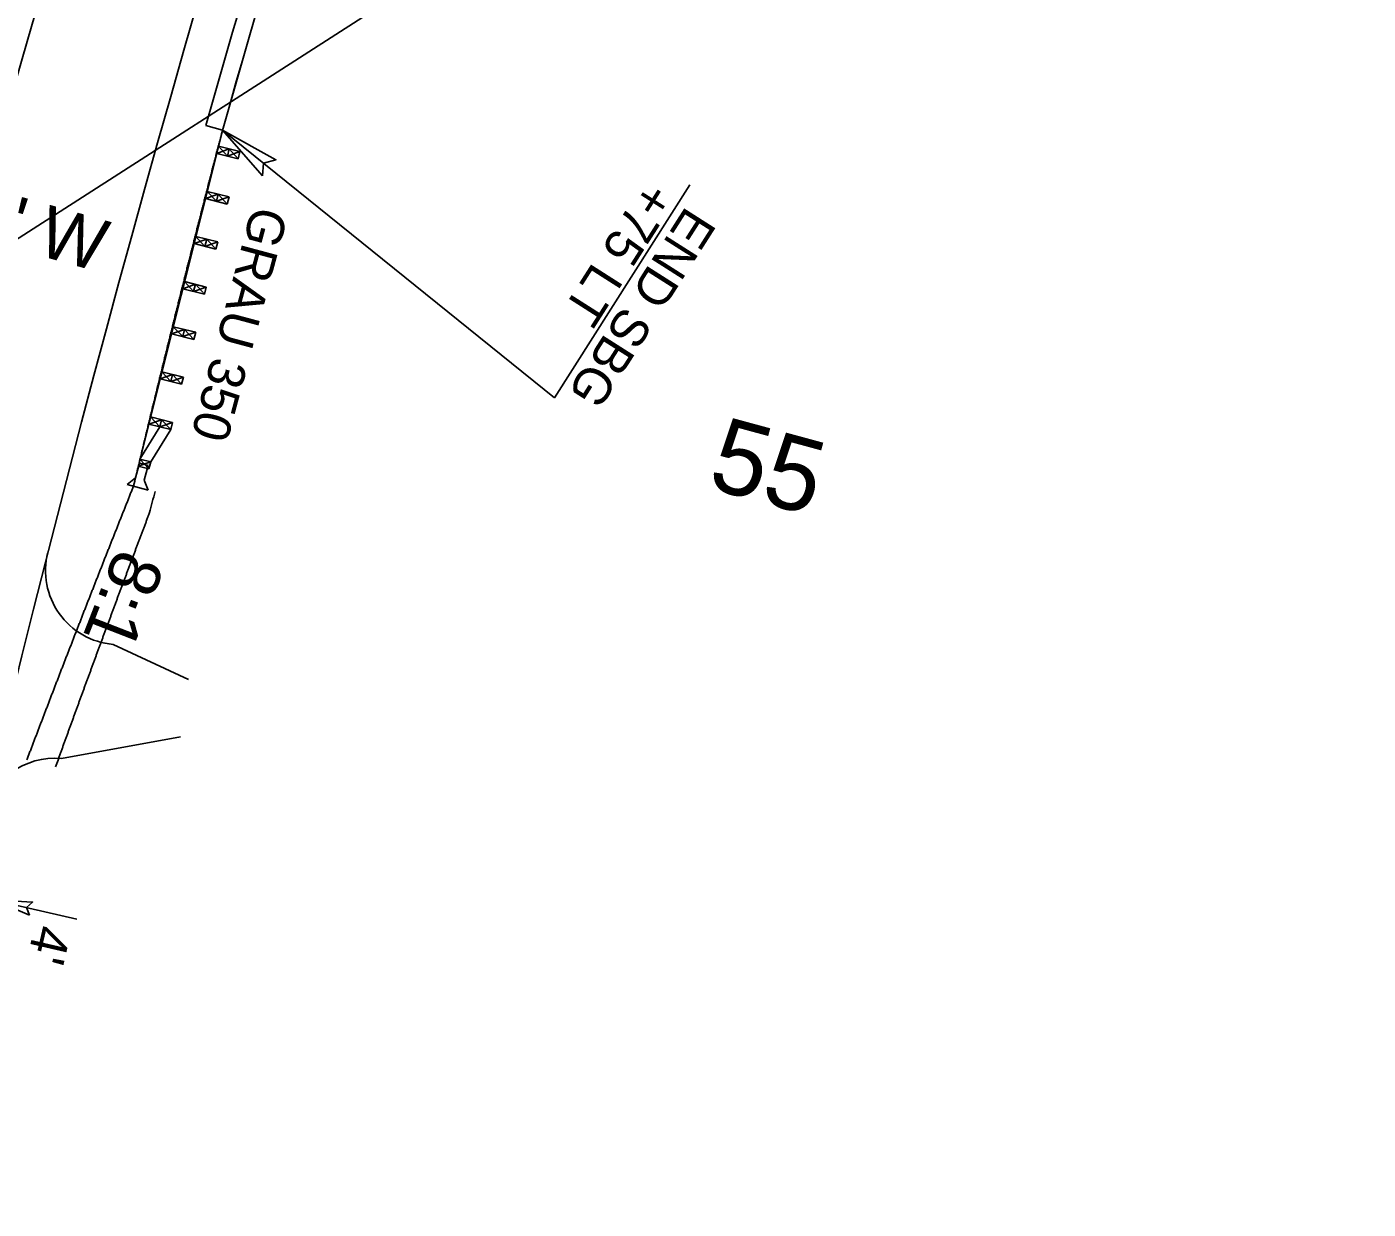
# Model space of a CAD drawing. Extents: x 1778969 to 1790720, y 807089 to 817794.
# Drawn here: x 1781068 to 1781249.7, y 812006.4 to 812166.6 of the extents above; entities that cross this region are included whole.
import ezdxf

# ---------------------------------------------------------------- set-up
doc = ezdxf.new("R2010")
doc.units = 0
for name, color, linetype in [('Prop CMT Guardrail Graphics', 7, 'Continuous'), ('Prop Conc Shoulder Berm Gutter', 7, 'Continuous'), ('Prop Dimension', 7, 'Continuous'), ('Prop Dimension Text', 7, 'Continuous'), ('Prop EOT', 7, 'Continuous'), ('Prop Guardrail', 7, 'Continuous'), ('Prop Guardrail Anchor Unit CELL', 7, 'Continuous'), ('Prop Horizontal Alignment', 7, 'Continuous'), ('Prop Horizontal Alignment Direction Label', 7, 'Continuous'), ('Prop Horizontal Alignment Station Label', 7, 'Continuous'), ('Prop Horizontal Alignment Tick Label', 7, 'Continuous'), ('Prop Paved Shoulder', 7, 'Continuous'), ('Prop Terminator CELL', 7, 'Continuous'), ('Scratch_Level_3', 7, 'Continuous'), ('Scratch_Level_7', 7, 'Continuous'), ('Scratch_Level_8', 7, 'Continuous')]:
    doc.layers.add(name, color=color, linetype=linetype)

msp = doc.modelspace()

# ---------------------------------------------------------------- linework, layer by layer
at = {"layer": 'Prop CMT Guardrail Graphics'}
msp.add_spline([(1781094.52, 812152.6), (1781094.27, 812151.67), (1781094.1, 812151.03), (1781093.93, 812150.38), (1781093.76, 812149.73), (1781093.59, 812149.09), (1781093.43, 812148.44), (1781093.26, 812147.8), (1781093.09, 812147.15), (1781092.93, 812146.5), (1781092.76, 812145.86), (1781092.59, 812145.21), (1781092.43, 812144.56), (1781092.26, 812143.92), (1781092.09, 812143.27), (1781091.93, 812142.63), (1781091.76, 812141.98), (1781091.6, 812141.33), (1781091.43, 812140.69), (1781091.27, 812140.04), (1781091.1, 812139.39), (1781090.94, 812138.75), (1781090.77, 812138.1), (1781090.61, 812137.45), (1781090.44, 812136.81), (1781090.28, 812136.16), (1781090.12, 812135.51), (1781089.95, 812134.86), (1781089.79, 812134.22), (1781089.62, 812133.57), (1781089.46, 812132.92), (1781089.3, 812132.28), (1781089.14, 812131.63), (1781088.97, 812130.98), (1781088.81, 812130.33), (1781088.65, 812129.69), (1781088.49, 812129.04), (1781088.33, 812128.39), (1781088.16, 812127.74), (1781088, 812127.1), (1781087.84, 812126.45), (1781087.68, 812125.8), (1781087.52, 812125.15), (1781087.36, 812124.51), (1781087.2, 812123.86), (1781087.04, 812123.21), (1781086.88, 812122.56), (1781086.72, 812121.92), (1781086.56, 812121.27), (1781086.4, 812120.62), (1781086.24, 812119.97), (1781086.08, 812119.32), (1781085.92, 812118.68), (1781085.76, 812118.03), (1781085.6, 812117.38), (1781085.45, 812116.73), (1781085.29, 812116.08), (1781085.13, 812115.43), (1781084.97, 812114.79), (1781084.81, 812114.14), (1781084.66, 812113.49), (1781084.5, 812112.84), (1781084.34, 812112.19), (1781084.19, 812111.54), (1781084.03, 812110.9), (1781083.87, 812110.25), (1781083.72, 812109.6), (1781083.56, 812108.95), (1781083.41, 812108.3), (1781083.25, 812107.65), (1781083.09, 812107), (1781082.94, 812106.35), (1781082.78, 812105.71), (1781082.47, 812104.41)], degree=3, dxfattribs=at)
at = {"layer": 'Prop Conc Shoulder Berm Gutter'}
msp.add_line((1781092.27, 812153.24), (1781094.52, 812152.6), dxfattribs=at)
msp.add_arc((1783308.81, 811525.98), 2303.58, 153.74801, 164.19896, dxfattribs=at)
at = {"layer": 'Prop Dimension'}
for p, q in [((1781139.47, 812116.33), (1781094.52, 812152.6)), ((1781139.47, 812116.33), (1781157.79, 812145.21)), ((1781063.52, 812048.31), (1781074.79, 812045.69))]:
    msp.add_line(p, q, dxfattribs=at)
at = {"layer": 'Prop EOT'}
for p, q in [((1781089.9, 812078.17), (1781079.7, 812082.94)), ((1781088.82, 812070.42), (1781072.7, 812067.48))]:
    msp.add_line(p, q, dxfattribs=at)
for centre, radius, start, end in [((1783308.81, 811525.98), 2309.25, 153.74801, 174.52695), ((1781080.55, 812092.9), 10, 165.7254, 265.109), ((1781071.84, 812057.52), 10, 85.109, 166.6335)]:
    msp.add_arc(centre, radius, start, end, dxfattribs=at)
at = {"layer": 'Prop Guardrail'}
msp.add_arc((1783308.81, 811525.98), 2301.25, 153.74801, 164.19128, dxfattribs=at)
at = {"layer": 'Prop Guardrail Anchor Unit CELL'}
for p, q in [((1781094.59, 812152.9), (1781083.21, 812107.56)), ((1781093.98, 812150.44), (1781093.73, 812149.47)), ((1781095.43, 812150.07), (1781093.73, 812149.47)), ((1781093.73, 812149.47), (1781096.64, 812148.74)), ((1781093.73, 812149.47), (1781095.19, 812149.1)), ((1781093.98, 812150.44), (1781096.88, 812149.71)), ((1781095.19, 812149.1), (1781093.98, 812150.44)), ((1781095.43, 812150.07), (1781095.19, 812149.1)), ((1781095.19, 812149.1), (1781096.88, 812149.71)), ((1781096.64, 812148.74), (1781095.43, 812150.07)), ((1781096.88, 812149.71), (1781096.64, 812148.74)), ((1781093.92, 812143.95), (1781092.2, 812143.35)), ((1781092.44, 812144.32), (1781095.4, 812143.58)), ((1781092.44, 812144.32), (1781093.68, 812142.98)), ((1781093.92, 812143.95), (1781093.68, 812142.98)), ((1781093.68, 812142.98), (1781095.4, 812143.58)), ((1781095.16, 812142.61), (1781093.92, 812143.95)), ((1781095.4, 812143.58), (1781095.16, 812142.61)), ((1781092.2, 812143.35), (1781095.16, 812142.61)), ((1781090.91, 812138.21), (1781093.86, 812137.47)), ((1781090.91, 812138.21), (1781092.14, 812136.87)), ((1781092.39, 812137.84), (1781090.66, 812137.24)), ((1781090.66, 812137.24), (1781093.62, 812136.5)), ((1781092.39, 812137.84), (1781092.14, 812136.87)), ((1781092.14, 812136.87), (1781093.86, 812137.47)), ((1781093.62, 812136.5), (1781092.39, 812137.84)), ((1781093.86, 812137.47), (1781093.62, 812136.5)), ((1781089.37, 812132.1), (1781089.13, 812131.13)), ((1781090.85, 812131.73), (1781089.13, 812131.13)), ((1781089.13, 812131.13), (1781092.07, 812130.39)), ((1781089.37, 812132.1), (1781092.32, 812131.36)), ((1781089.37, 812132.1), (1781090.6, 812130.76)), ((1781090.85, 812131.73), (1781090.6, 812130.76)), ((1781090.6, 812130.76), (1781092.32, 812131.36)), ((1781092.07, 812130.39), (1781090.85, 812131.73)), ((1781092.32, 812131.36), (1781092.07, 812130.39)), ((1781089.36, 812125.61), (1781087.59, 812125.02)), ((1781087.84, 812125.99), (1781090.88, 812125.23)), ((1781087.84, 812125.99), (1781089.12, 812124.64)), ((1781089.36, 812125.61), (1781089.12, 812124.64)), ((1781090.64, 812124.26), (1781089.36, 812125.61)), ((1781087.59, 812125.02), (1781090.64, 812124.26)), ((1781089.12, 812124.64), (1781090.88, 812125.23)), ((1781090.88, 812125.23), (1781090.64, 812124.26)), ((1781087.76, 812119.51), (1781086.06, 812118.91)), ((1781086.06, 812118.91), (1781088.97, 812118.18)), ((1781086.3, 812119.88), (1781089.21, 812119.15)), ((1781086.3, 812119.88), (1781087.52, 812118.54)), ((1781087.76, 812119.51), (1781087.52, 812118.54)), ((1781087.52, 812118.54), (1781089.21, 812119.15)), ((1781088.97, 812118.18), (1781087.76, 812119.51)), ((1781089.21, 812119.15), (1781088.97, 812118.18)), ((1781086.26, 812113.39), (1781084.53, 812112.8)), ((1781084.53, 812112.8), (1781087.5, 812112.05)), ((1781084.77, 812113.77), (1781087.74, 812113.02)), ((1781084.77, 812113.77), (1781086.01, 812112.42)), ((1781086.26, 812113.39), (1781086.01, 812112.42)), ((1781086.01, 812112.42), (1781087.74, 812113.02)), ((1781087.5, 812112.05), (1781086.26, 812113.39)), ((1781087.74, 812113.02), (1781087.5, 812112.05)), ((1781086.01, 812112.42), (1781083.33, 812108.04)), ((1781087.5, 812112.05), (1781084.79, 812107.68)), ((1781083.28, 812107.51), (1781082.74, 812105.53)), ((1781083.09, 812107.07), (1781084.79, 812107.68)), ((1781083.87, 812107.35), (1781083.28, 812107.51)), ((1781083.33, 812108.04), (1781084.79, 812107.68)), ((1781084.54, 812106.71), (1781083.33, 812108.04)), ((1781084.46, 812107.19), (1781083.87, 812107.35)), ((1781084.79, 812107.68), (1781084.54, 812106.71)), ((1781084.79, 812107.68), (1781084.67, 812107.19)), ((1781082.74, 812105.53), (1781081.6, 812104.62)), ((1781083.09, 812107.07), (1781084.54, 812106.71)), ((1781083.92, 812105.21), (1781084.46, 812107.19)), ((1781081.6, 812104.62), (1781084.44, 812103.85)), ((1781084.44, 812103.85), (1781083.92, 812105.21))]:
    msp.add_line(p, q, dxfattribs=at)
at = {"layer": 'Prop Horizontal Alignment'}
msp.add_arc((1783308.81, 811525.98), 2330, 144.08998, 185.35942, dxfattribs=at)
at = {"layer": 'Prop Horizontal Alignment Station Label'}
msp.add_line((1781060.57, 812133.95), (1781190.63, 812217.49), dxfattribs=at)
at = {"layer": 'Prop Paved Shoulder'}
for points in [[(1781094.52, 812152.6), (1781094.27, 812151.67), (1781094.1, 812151.03), (1781093.93, 812150.38), (1781093.76, 812149.73), (1781093.59, 812149.09), (1781093.43, 812148.44), (1781093.26, 812147.8), (1781093.09, 812147.15), (1781092.93, 812146.5), (1781092.76, 812145.86), (1781092.59, 812145.21), (1781092.43, 812144.56), (1781092.26, 812143.92), (1781092.09, 812143.27), (1781091.93, 812142.63), (1781091.76, 812141.98), (1781091.6, 812141.33), (1781091.43, 812140.69), (1781091.27, 812140.04), (1781091.1, 812139.39), (1781090.94, 812138.75), (1781090.77, 812138.1), (1781090.61, 812137.45), (1781090.44, 812136.81), (1781090.28, 812136.16), (1781090.12, 812135.51), (1781089.95, 812134.86), (1781089.79, 812134.22), (1781089.62, 812133.57), (1781089.46, 812132.92), (1781089.3, 812132.28), (1781089.14, 812131.63), (1781088.97, 812130.98), (1781088.81, 812130.33), (1781088.65, 812129.69), (1781088.49, 812129.04), (1781088.33, 812128.39), (1781088.16, 812127.74), (1781088, 812127.1), (1781087.84, 812126.45), (1781087.68, 812125.8), (1781087.52, 812125.15), (1781087.36, 812124.51), (1781087.2, 812123.86), (1781087.04, 812123.21), (1781086.88, 812122.56), (1781086.72, 812121.92), (1781086.56, 812121.27), (1781086.4, 812120.62), (1781086.24, 812119.97), (1781086.08, 812119.32), (1781085.92, 812118.68), (1781085.76, 812118.03), (1781085.6, 812117.38), (1781085.45, 812116.73), (1781085.29, 812116.08), (1781085.13, 812115.43), (1781084.97, 812114.79), (1781084.81, 812114.14), (1781084.66, 812113.49), (1781084.5, 812112.84), (1781084.34, 812112.19), (1781084.19, 812111.54), (1781084.03, 812110.9), (1781083.87, 812110.25), (1781083.72, 812109.6), (1781083.56, 812108.95), (1781083.41, 812108.3), (1781083.25, 812107.65), (1781083.09, 812107), (1781082.94, 812106.35), (1781082.78, 812105.71), (1781082.47, 812104.41)], [(1781082.47, 812104.41), (1781082.27, 812103.91), (1781082.07, 812103.41), (1781081.88, 812102.91), (1781081.68, 812102.41), (1781081.48, 812101.91), (1781081.28, 812101.41), (1781081.08, 812100.91), (1781080.88, 812100.41), (1781080.68, 812099.91), (1781080.48, 812099.41), (1781080.29, 812098.91), (1781080.09, 812098.41), (1781079.89, 812097.91), (1781079.69, 812097.41), (1781079.49, 812096.91), (1781079.29, 812096.41), (1781079.1, 812095.91), (1781078.9, 812095.41), (1781078.7, 812094.91), (1781078.5, 812094.4), (1781078.31, 812093.9), (1781078.11, 812093.4), (1781077.91, 812092.9), (1781077.72, 812092.4), (1781077.52, 812091.9), (1781077.32, 812091.4), (1781077.13, 812090.9), (1781076.93, 812090.4), (1781076.73, 812089.9), (1781076.54, 812089.39), (1781076.34, 812088.89), (1781076.14, 812088.39), (1781075.95, 812087.89), (1781075.75, 812087.39), (1781075.56, 812086.89), (1781075.36, 812086.39), (1781075.17, 812085.88), (1781074.97, 812085.38), (1781074.78, 812084.88), (1781074.58, 812084.38), (1781074.38, 812083.88), (1781074.19, 812083.37), (1781074, 812082.87), (1781073.8, 812082.37), (1781073.61, 812081.87), (1781073.41, 812081.37), (1781073.22, 812080.86), (1781073.02, 812080.36), (1781072.83, 812079.86), (1781072.63, 812079.36), (1781072.44, 812078.85), (1781072.25, 812078.35), (1781072.05, 812077.85), (1781071.86, 812077.35), (1781071.67, 812076.84), (1781071.47, 812076.34), (1781071.28, 812075.84), (1781071.09, 812075.33), (1781070.89, 812074.83), (1781070.7, 812074.33), (1781070.51, 812073.82), (1781070.32, 812073.32), (1781070.12, 812072.82), (1781069.93, 812072.31), (1781069.74, 812071.81), (1781069.55, 812071.31), (1781069.35, 812070.8), (1781069.16, 812070.3), (1781068.97, 812069.8), (1781068.78, 812069.29), (1781068.59, 812068.79), (1781068.39, 812068.29), (1781068.01, 812067.28)]]:
    msp.add_spline(points, degree=3, dxfattribs=at)
at = {"layer": 'Prop Terminator CELL'}
for points in [[(1781099.94, 812146.43), (1781094.52, 812152.6), (1781101.76, 812148.61), (1781100.05, 812148.14)], [(1781068.36, 812046.27), (1781063.52, 812048.31), (1781068.8, 812048.03), (1781067.95, 812047.28)]]:
    msp.add_lwpolyline(points, close=True, dxfattribs=at)
at = {"layer": 'Scratch_Level_3'}
msp.add_arc((1783308.81, 811525.98), 2350.75, 144.08998, 164.89021, dxfattribs=at)
at = {"layer": 'Scratch_Level_7'}
msp.add_line((1781094.59, 812152.9), (1781094.51, 812152.61), dxfattribs=at)
msp.add_arc((1783308.81, 811525.98), 2301.26, 153.74801, 164.19128, dxfattribs=at)
at = {"layer": 'Scratch_Level_8'}
msp.add_arc((1783308.81, 811525.98), 2297.25, 165.43586, 165.50963, dxfattribs=at)
msp.add_spline([(1781084.64, 812100.79), (1781084.46, 812100.33), (1781084.28, 812099.86), (1781084.11, 812099.4), (1781083.93, 812098.93), (1781083.76, 812098.47), (1781083.58, 812098.01), (1781083.41, 812097.54), (1781083.23, 812097.08), (1781083.06, 812096.61), (1781082.88, 812096.15), (1781082.71, 812095.69), (1781082.53, 812095.22), (1781082.36, 812094.76), (1781082.19, 812094.29), (1781082.01, 812093.83), (1781081.84, 812093.36), (1781081.66, 812092.9), (1781081.49, 812092.43), (1781081.31, 812091.97), (1781081.14, 812091.5), (1781080.97, 812091.04), (1781080.79, 812090.57), (1781080.62, 812090.11), (1781080.45, 812089.65), (1781080.27, 812089.18), (1781080.1, 812088.72), (1781079.93, 812088.25), (1781079.75, 812087.78), (1781079.58, 812087.32), (1781079.41, 812086.85), (1781079.24, 812086.39), (1781079.06, 812085.92), (1781078.89, 812085.46), (1781078.72, 812084.99), (1781078.55, 812084.53), (1781078.37, 812084.06), (1781078.2, 812083.6), (1781078.03, 812083.13), (1781077.86, 812082.67), (1781077.69, 812082.2), (1781077.51, 812081.73), (1781077.34, 812081.27), (1781077.17, 812080.8), (1781077, 812080.34), (1781076.83, 812079.87), (1781076.66, 812079.4), (1781076.49, 812078.94), (1781076.31, 812078.47), (1781076.14, 812078.01), (1781075.97, 812077.54), (1781075.8, 812077.07), (1781075.63, 812076.61), (1781075.46, 812076.14), (1781075.29, 812075.68), (1781075.12, 812075.21), (1781074.95, 812074.74), (1781074.78, 812074.28), (1781074.61, 812073.81), (1781074.44, 812073.34), (1781074.27, 812072.88), (1781074.1, 812072.41), (1781073.93, 812071.94), (1781073.76, 812071.48), (1781073.59, 812071.01), (1781073.42, 812070.54), (1781073.25, 812070.08), (1781073.08, 812069.61), (1781072.91, 812069.14), (1781072.74, 812068.67), (1781072.57, 812068.21), (1781072.41, 812067.74), (1781072.24, 812067.27), (1781071.9, 812066.34)], degree=3, dxfattribs=at)

# ---------------------------------------------------------------- texts
at = {"layer": 'Prop Dimension Text'}
for s, height, rotation, p in [('+75 LT', 5, 237.4943, (1781151.81, 812146)), ('END SBG', 5, 237.4943, (1781157.34, 812142.48)), ('8:1', 7, 248.7194, (1781080.27, 812096.21)), ("4'", 5, 256.9847, (1781069.15, 812045.15))]:
    msp.add_text(s, height=height, rotation=rotation, dxfattribs=at).set_placement(p)
at = {"layer": 'Prop Guardrail Anchor Unit CELL'}
msp.add_text('GRAU 350', height=5, rotation=254.9827, dxfattribs=at).set_placement((1781098.61, 812142.54))
at = {"layer": 'Prop Horizontal Alignment Direction Label'}
msp.add_text('N 74%%d 18\' 50.5" W', height=7, rotation=344.314, dxfattribs=at).set_placement((1781006.52, 812153.37))
at = {"layer": 'Prop Horizontal Alignment Tick Label'}
msp.add_text('55', height=10, rotation=344.8137, dxfattribs=at).set_placement((1781159.97, 812104.23))

doc.saveas('drawing.dxf')
